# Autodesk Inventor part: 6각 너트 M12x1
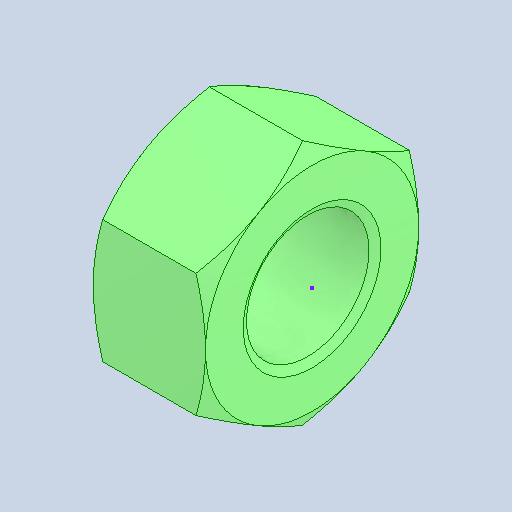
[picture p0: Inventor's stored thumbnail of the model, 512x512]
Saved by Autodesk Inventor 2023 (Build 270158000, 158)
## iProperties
Created: 2025-04
Part Number: 6각 너트 M12x1
Material: 강철, 연강
Description: 6각 너트
Document SubType Name: Modeling
Designer: ADMIN_PC
Density: 7.85 g/cm^3
Appearance: 기본값
Author: jhkim
Sending System: Autodesk Inventor 2026
Preprocessor: ST-DEVELOPER v20.1
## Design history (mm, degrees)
node "복구된 형상1"
  node "스케치1"
feature "Solid1"
node "스케치3"
node "솔리드1"
